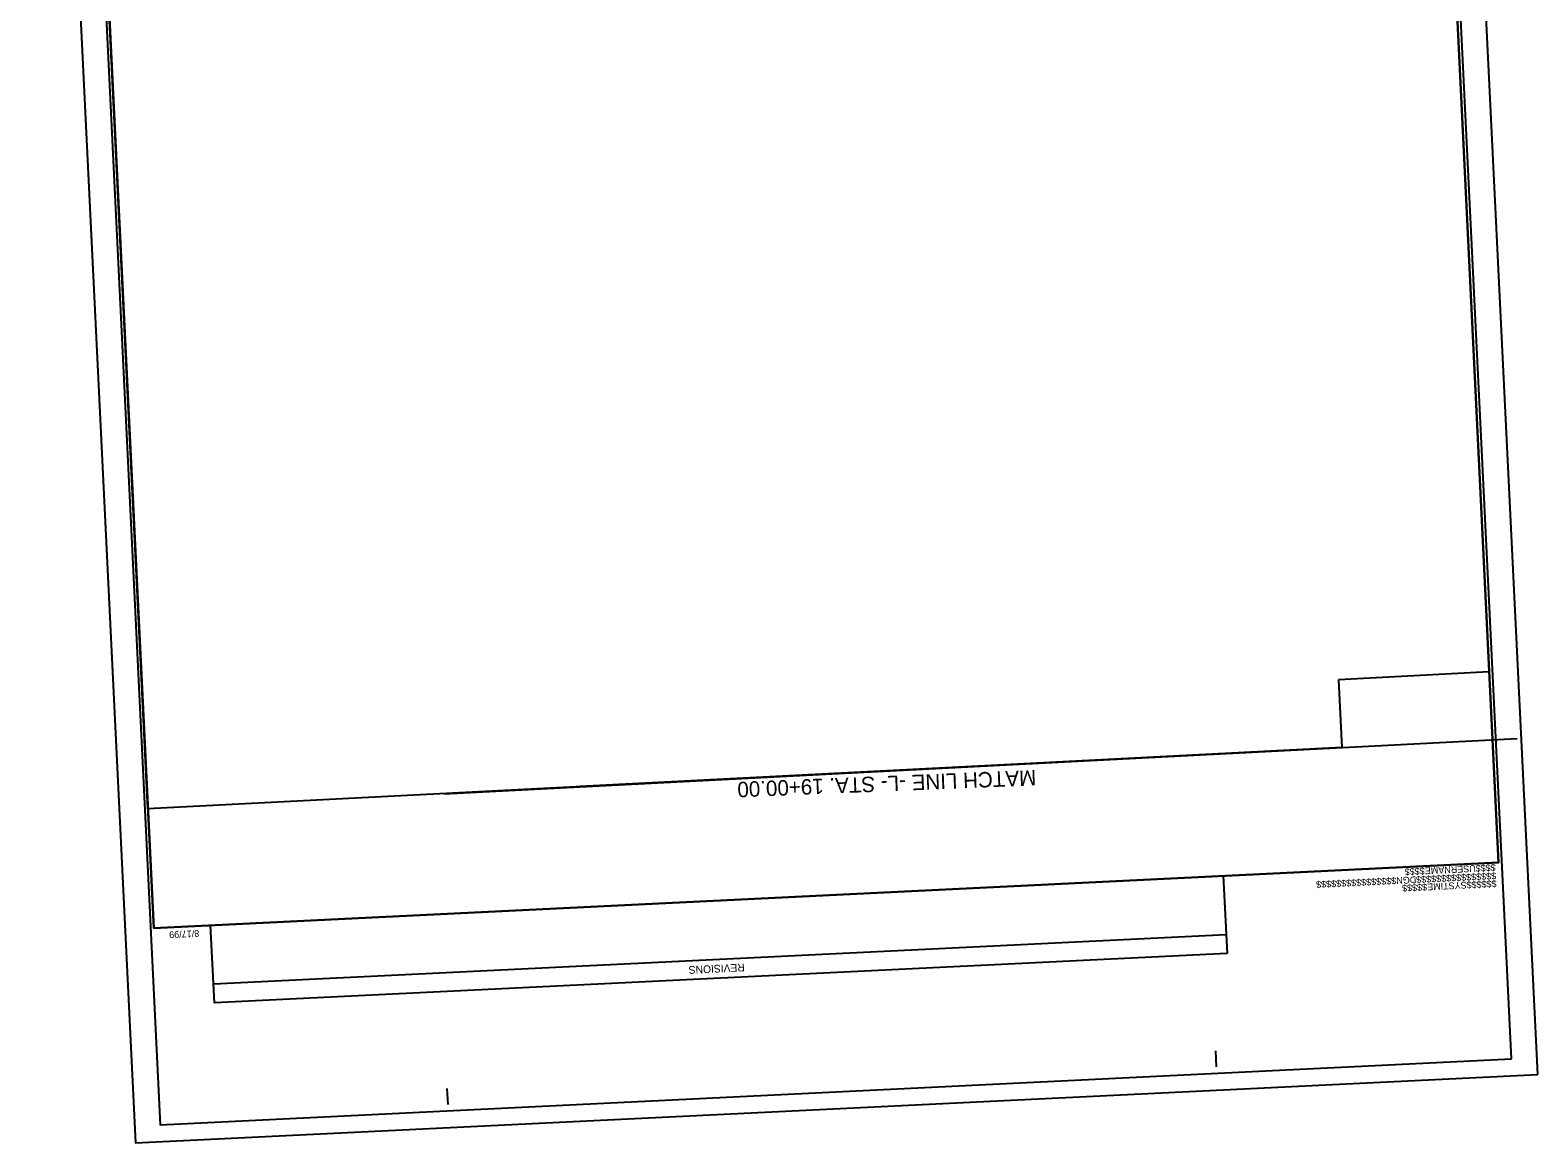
# Model space of a CAD drawing. Extents: x 2368277 to 2369452, y 801942 to 803676.
# Drawn here: x 2368277 to 2369452, y 801942 to 802809 of the extents above; entities that cross this region are included whole.
import ezdxf

# ---------------------------------------------------------------- set-up
doc = ezdxf.new("R2010")
doc.units = 0
for name, color, linetype in [('Default', 7, 'Continuous'), ('Old_Level_10', 7, 'Continuous'), ('Old_Level_15', 7, 'Continuous'), ('Old_Level_18', 7, 'Continuous'), ('Old_Level_2', 7, 'Continuous'), ('Old_Level_4', 7, 'Continuous'), ('Old_Level_6', 7, 'Continuous'), ('Old_Level_62', 7, 'Continuous'), ('Plot Label CELL', 7, 'Continuous'), ('Plot Shape CELL', 7, 'Continuous'), ('User Information Notes CELL', 7, 'Continuous')]:
    doc.layers.add(name, color=color, linetype=linetype)

msp = doc.modelspace()

# ---------------------------------------------------------------- linework, layer by layer
at = {"layer": 'Default'}
msp.add_line((2368599.6, 802213.8), (2369436.2, 802256.8), dxfattribs=at)
at = {"layer": 'Old_Level_10'}
msp.add_lwpolyline([(2368373.1, 802109), (2369421.9, 802160.1), (2369348.8, 803658.4), (2368511.3, 803617.5), (2368522.9, 803378.5), (2368311.7, 803368.2)], close=True, dxfattribs=at)
at = {"layer": 'Old_Level_15'}
for p, q in [((2369452.5, 801994.9), (2369370.4, 803676.4)), ((2368276.7, 803623.1), (2368358.8, 801941.6)), ((2368358.8, 801941.6), (2369452.5, 801994.9))]:
    msp.add_line(p, q, dxfattribs=at)
at = {"layer": 'Old_Level_18'}
msp.add_line((2369184, 802243.8), (2368705.6, 802219.3), dxfattribs=at)
at = {"layer": 'Old_Level_2'}
msp.add_lwpolyline([(2369296.9, 802302.5), (2369299.5, 802249.8), (2368368.6, 802201.9), (2368311.7, 803368.2), (2368522.9, 803378.5), (2368516.4, 803512), (2369216.7, 803546.4), (2369252.9, 803653.7), (2369348.8, 803658.4), (2369414.6, 802308.9)], close=True, dxfattribs=at)
msp.add_lwpolyline([(2369296.9, 802302.5), (2369299.5, 802249.8), (2368368.6, 802201.9), (2368311.7, 803368.2), (2368522.9, 803378.5), (2368516.4, 803512), (2369216.7, 803546.4), (2369252.9, 803653.7), (2369348.8, 803658.4), (2369414.6, 802308.9)], close=True, dxfattribs=at)
at = {"layer": 'Old_Level_4'}
msp.add_lwpolyline([(2369431.8, 802007), (2369350.7, 803671), (2368296.9, 803619.6), (2368378.1, 801955.6)], close=True, dxfattribs=at)
at = {"layer": 'Old_Level_6'}
msp.add_lwpolyline([(2369452.5, 801994.9), (2369370.4, 803676.4), (2368276.7, 803623.1), (2368358.8, 801941.6)], close=True, dxfattribs=at)
at = {"layer": 'Plot Label CELL'}
msp.add_line((2368911.6, 802229.8), (2368911.6, 802229.8), dxfattribs=at)
at = {"layer": 'Plot Shape CELL'}
for p, q in [((2369421.9, 802160.1), (2369421.9, 802160.1)), ((2368373.1, 802109), (2368373.1, 802109)), ((2369201.9, 802000.8), (2369201.3, 802013.2)), ((2368602.6, 801971.5), (2368602, 801984))]:
    msp.add_line(p, q, dxfattribs=at)
for points in [[(2368300, 803607.2), (2368373.1, 802109), (2369421.9, 802160.1), (2369348.8, 803658.4)], [(2369421.9, 802160.1), (2368373.1, 802109), (2368309.7, 803407.4), (2368459.6, 803414.7), (2368449.9, 803614.5), (2369348.8, 803658.4)]]:
    msp.add_lwpolyline(points, close=True, dxfattribs=at)
at = {"layer": 'User Information Notes CELL'}
msp.add_line((2369209.4, 802103.7), (2368419.7, 802065.2), dxfattribs=at)
msp.add_lwpolyline([(2369210.1, 802089.2), (2368420.4, 802050.7), (2368417.4, 802111.2), (2369207.1, 802149.7)], close=True, dxfattribs=at)

# ---------------------------------------------------------------- texts
at = {"layer": 'Old_Level_62'}
msp.add_text('MATCH LINE -L- STA. 19+00.00', height=12, rotation=182.302, dxfattribs=at).set_placement((2369061, 802232.3))
at = {"layer": 'Plot Shape CELL'}
for s, p in [('$$$$USERNAME$$$$', (2369419.5, 802158.9)), ('$$$$$$$$$$$$$$$$DGN$$$$$$$$$$$$$$$$', (2369419.9, 802152.4)), ('$$$$$$SYSTIME$$$$$', (2369420.2, 802146.3)), ('8/17/99', (2368408.4, 802107.5))]:
    msp.add_text(s, height=5.25, rotation=182.7929, dxfattribs=at).set_placement(p)
at = {"layer": 'User Information Notes CELL'}
msp.add_text('REVISIONS', height=6, rotation=182.7929, dxfattribs=at).set_placement((2368833.8, 802081.4))

doc.saveas('drawing.dxf')
